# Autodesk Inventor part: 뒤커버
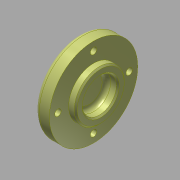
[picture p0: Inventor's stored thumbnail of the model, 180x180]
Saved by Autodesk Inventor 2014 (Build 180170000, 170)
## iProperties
Created: 2015-12
Part Number: 뒤커버
Document SubType Name: Modeling
Designer: mdu
Density: 2.71 g/cm^3
Material: 알루미늄 6061
Mass: 80.8084 g
Surface Area: 93.036 cm^2
Volume: 29.8186 cm^3
Appearance: 알루미늄 - 평지
Author: mdu
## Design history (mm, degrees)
sketch "스케치1"
  geometry: L1 (-7.5, 0)-(7.5, 0); L2 (-7.5, 0)-(-7.5, 31); L3 (-7.5, 31)-(2.5, 31); L4 (2.5, 31)-(2.5, 17.5); L5 (2.5, 17.5)-(7.5, 17.5); L6 (7.5, 17.5)-(7.5, 0); 2 further points
  constraints: 12 end point, 3 parallel, 1 coincident, 1 horizontal, 1 midpoint, 1 perpendicular
  dimensions: "d0" = 15 distance of L1.start L1.end; "d1" = 62 diameter of L3 L1; "d2" = 35 diameter of L5 L1; "d34" = 10 distance of L2.end L3.end
revolve "회전1" sketch "스케치1" stored, may be unused: angle "d6" = 90 deg
sketch "스케치2" dims "d32" = 50
  geometry: 3 further points
  constraints: 2 vertical alignment, 1 coincident, 2 other
hole "구멍1" sketch "스케치2" at (0, 25) diameter "d8" = 4.5; stored, may be unused: countersink angle "d12" = 90 deg, drill point angle "d14" = 118 deg; dims "d9" = 6, "d10" = 8, "d11" = 4.4, "d13" = 8
hole "구멍2" diameter "d20" = 24; stored, may be unused: countersink angle "d24" = 90 deg, drill point angle "d26" = 0 deg; dims "d18" = 10, "d19" = 10, "d21" = 6, "d22" = 8, "d23" = 4.4, "d25" = 8
fillet "모깎기1" dims "d27" = 3
fillet "모깎기2" dims "d28" = 3
chamfer "모따기1" distance "d29" = 1; stored, may be unused: second distance "d30" = 2, angle "d31" = 45 deg
node "솔리드1"
pattern_circular "원형 패턴1" dims angle "d16" = 360 deg
